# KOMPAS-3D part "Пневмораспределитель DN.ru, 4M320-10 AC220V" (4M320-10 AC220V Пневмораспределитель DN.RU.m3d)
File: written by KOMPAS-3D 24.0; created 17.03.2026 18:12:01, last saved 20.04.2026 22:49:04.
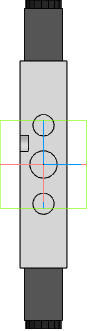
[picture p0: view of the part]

Document properties: Автор: R2D2; Полное имя файла: E:\Работа\Зайцев\Аксессуары для пневмоприводов\Пневмораспределители DN.ru\4M320 AC220V Пневмораспределитель DN.RU\4M320-10 AC220V Пневмораспределитель DN.RU\4M320-10 AC220V Пневмораспределитель DN.RU.m3d

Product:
- Part/product: Пневмораспределитель DN.ru  | designation 4M320-10 AC220V
    Масса: 1.2
    Раздел спецификации: Прочие изделия
    Примечание: D290-00365

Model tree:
1. Операция без истории:1

Expressions: 4M320-10 AC220V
